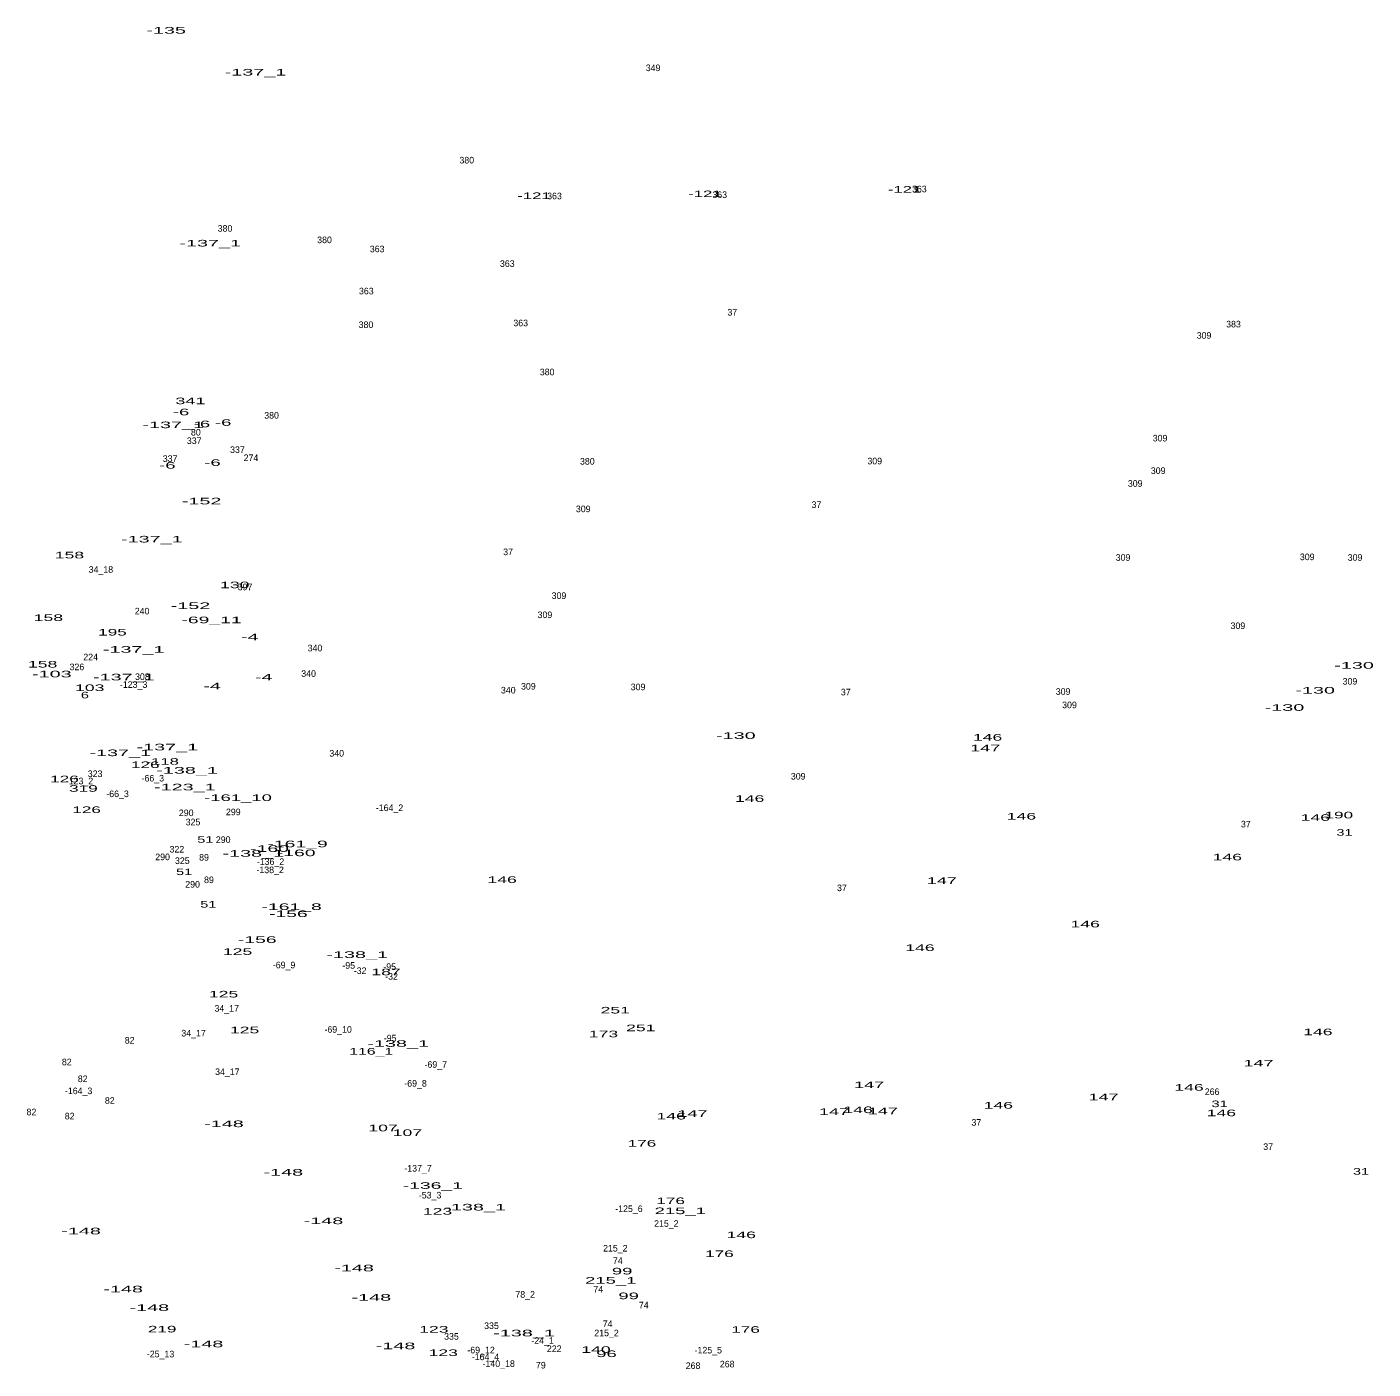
# Model space of a CAD drawing. Extents: x -662499 to -659675, y -1001682 to -998165.
# Drawn here: x -661283 to -660465, y -999146 to -998330 of the extents above; entities that cross this region are included whole.
import ezdxf
from ezdxf.enums import TextEntityAlignment as Align

# ---------------------------------------------------------------- set-up
doc = ezdxf.new("R2010")
doc.units = 0
doc.header["$LTSCALE"] = 1.6
doc.layers.add('24', color=7, linetype='Continuous')

msp = doc.modelspace()

# ---------------------------------------------------------------- texts
at = {"layer": '24'}
for s, width, p in [('-135', 2.25, (-661198.121, -998334.15)), ('-137_1', 2.25, (-661143.793, -998359.62)), ('-121', 1.9, (-660974.547, -998434.72)), ('-121', 1.9, (-660870.627, -998433.55)), ('-121', 1.9, (-660749.267, -998430.84)), ('-137_1', 2.25, (-661171.323, -998463.53)), ('-6', 2.1, (-661189.059, -998566.17)), ('341', 2.05, (-661183.393, -998559.39)), ('-137_1', 2.25, (-661193.813, -998573.96)), ('-6', 2.1, (-661176.359, -998573.44)), ('-6', 2.1, (-661163.469, -998572.57)), ('-6', 2.1, (-661197.399, -998598.56)), ('-6', 2.1, (-661169.959, -998596.91)), ('-152', 2.25, (-661176.561, -998620.3)), ('-137_1', 2.25, (-661206.803, -998643.45)), ('158', 2, (-661256.897, -998653.14)), ('130', 2, (-661156.424, -998671.24)), ('-152', 2.25, (-661183.341, -998683.91)), ('158', 2, (-661269.687, -998691.15)), ('-69_11', 2.2, (-661170.527, -998692.53)), ('195', 1.95, (-661230.753, -998700.01)), ('-4', 2.25, (-661147.28, -998702.86)), ('-137_1', 2.25, (-661217.853, -998710.46)), ('158', 2, (-661273.177, -998719.47)), ('-130', 2.25, (-660476.077, -998720.17)), ('-103', 2.25, (-661267.617, -998725.43)), ('-137_1', 2.25, (-661223.853, -998727.29)), ('-4', 2.25, (-661138.75, -998727.3)), ('103', 2, (-661244.584, -998733.76)), ('6', 1.65, (-661247.506, -998738.22)), ('-4', 2.25, (-661170.16, -998732.73)), ('-130', 2.25, (-660499.727, -998735.3)), ('-130', 2.25, (-660518.347, -998745.77)), ('-130', 2.25, (-660851.837, -998762.84)), ('-137_1', 2.25, (-661197.403, -998769.82)), ('147', 2.05, (-660700.258, -998770.41)), ('146', 2, (-660698.818, -998763.9)), ('-137_1', 2.25, (-661226.003, -998773.31)), ('-118', 1.9, (-661200.527, -998778.56)), ('126', 1.95, (-661210.843, -998780.58)), ('-138_1', 2.25, (-661185.407, -998783.93)), ('126', 1.95, (-661259.933, -998789.2)), ('319', 1.95, (-661248.403, -998794.98)), ('-123_1', 2.25, (-661186.747, -998794.14)), ('-161_10', 2.1, (-661154.445, -998800.59)), ('146', 2, (-660843.448, -998801.13)), ('126', 1.95, (-661246.473, -998807.89)), ('146', 2, (-660678.268, -998811.87)), ('190', 1.95, (-660485.349, -998811.16)), ('146', 2, (-660499.598, -998812.63)), ('51', 1.65, (-661174.317, -998825.98)), ('-161_9', 2.2, (-661118.237, -998828.7)), ('31', 1.65, (-660481.887, -998821.69)), ('-138_1', 2.25, (-661145.137, -998834.46)), ('-160', 2.2, (-661135.251, -998831.51)), ('-160', 2.2, (-661119.061, -998834.12)), ('146', 2, (-660553.108, -998836.68)), ('51', 1.65, (-661187.187, -998845.64)), ('146', 2, (-660993.888, -998850.39)), ('147', 2.05, (-660726.628, -998851)), ('51', 1.65, (-661172.477, -998865.39)), ('-161_8', 2.2, (-661121.833, -998866.84)), ('-156', 2.2, (-661123.845, -998871.13)), ('146', 2, (-660639.498, -998877.42)), ('125', 2, (-661154.697, -998894.14)), ('-156', 2.2, (-661142.745, -998886.84)), ('146', 2, (-660739.918, -998891.77)), ('-138_1', 2.25, (-661081.997, -998895.96)), ('187', 2, (-661064.473, -998906.48)), ('125', 2, (-661163.217, -998920)), ('251', 2, (-660925.127, -998929.74)), ('125', 2, (-661150.437, -998941.79)), ('251', 2, (-660909.617, -998940.51)), ('146', 2, (-660498.048, -998942.95)), ('-138_1', 2.25, (-661057.077, -998950.01)), ('173', 2, (-660932.283, -998944.19)), ('116_1', 1.8, (-661073.476, -998954.72)), ('147', 2.05, (-660534.118, -998961.94)), ('147', 2.05, (-660770.828, -998975.12)), ('147', 2.05, (-660628.338, -998982.49)), ('146', 2, (-660576.378, -998976.7)), ('147', 2.05, (-660792.158, -998991.41)), ('146', 2, (-660777.528, -998990.3)), ('147', 2.05, (-660762.488, -998991.03)), ('146', 2, (-660692.308, -998987.56)), ('146', 2, (-660556.718, -998992.19)), ('31', 1.65, (-660557.787, -998986.67)), ('-148', 2.25, (-661162.976, -998998.81)), ('146', 2, (-660891.138, -998994.17)), ('147', 2.05, (-660878.228, -998992.58)), ('107', 2, (-661066.279, -999001.33)), ('107', 2, (-661051.469, -999004.23)), ('176', 1.95, (-660908.917, -999010.69)), ('-148', 2.25, (-661126.916, -999028.29)), ('31', 1.65, (-660471.817, -999027.73)), ('-136_1', 2.2, (-661036.043, -999036.32)), ('-138_1', 2.25, (-661010.297, -999049.47)), ('176', 1.95, (-660891.467, -999045.6)), ('-148', 2.25, (-661102.486, -999057.77)), ('123', 2, (-661033.177, -999052.01)), ('215_1', 2.1, (-660885.615, -999051.7)), ('-148', 2.25, (-661249.826, -999063.98)), ('146', 2, (-660848.568, -999066.3)), ('176', 1.95, (-660861.807, -999077.79)), ('-148', 2.25, (-661083.876, -999086.47)), ('99', 2.1, (-660920.961, -999088.36)), ('215_1', 2.1, (-660927.875, -999093.97)), ('-148', 2.25, (-661224.236, -999099.27)), ('-148', 2.25, (-661073.406, -999104.32)), ('99', 2.1, (-660916.991, -999103.38)), ('-148', 2.25, (-661208.346, -999110.52)), ('219', 1.95, (-661200.573, -999123.61)), ('123', 2, (-661035.407, -999123.71)), ('-138_1', 2.25, (-660980.577, -999126)), ('176', 1.95, (-660845.947, -999123.83)), ('-148', 2.25, (-661175.386, -999132.63)), ('-148', 2.25, (-661058.676, -999133.79)), ('123', 2, (-661029.687, -999137.95)), ('140', 2, (-660936.859, -999136.03)), ('96', 2.1, (-660930.461, -999138.6))]:
    msp.add_text(s, height=4, dxfattribs=dict(at, width=width)).set_placement(p, align=Align.CENTER)
for s, p in [('349', (-660902.107, -998356.95)), ('380', (-661015.391, -998413.08)), ('363', (-660962.073, -998434.85)), ('363', (-660861.653, -998434.07)), ('363', (-660740.293, -998430.58)), ('380', (-661162.341, -998454.54)), ('380', (-661101.851, -998461.52)), ('363', (-661069.863, -998467.04)), ('363', (-660990.773, -998475.96)), ('363', (-661076.463, -998492.64)), ('37', (-660853.973, -998505.5)), ('380', (-661076.651, -998513.12)), ('363', (-660982.623, -998512.03)), ('383', (-660549.357, -998512.74)), ('309', (-660567.227, -998519.6)), ('380', (-660966.531, -998541.82)), ('380', (-661134.041, -998568.19)), ('80', (-661180.071, -998578.45)), ('309', (-660593.977, -998582.05)), ('337', (-661181.063, -998583.62)), ('337', (-661154.793, -998589.05)), ('337', (-661195.693, -998594.48)), ('274', (-661146.557, -998593.97)), ('380', (-660942.111, -998596.12)), ('309', (-660767.417, -998595.95)), ('309', (-660595.137, -998601.83)), ('309', (-660609.097, -998609.59)), ('37', (-660802.853, -998622.5)), ('309', (-660944.607, -998625.04)), ('37', (-660990.293, -998651.16)), ('309', (-660616.467, -998654.59)), ('309', (-660504.527, -998654.2)), ('309', (-660475.447, -998654.59)), ('34_18', (-661237.773, -998661.88)), ('397', (-661150.178, -998672.48)), ('309', (-660959.347, -998677.79)), ('240', (-661212.745, -998687.19)), ('309', (-660967.877, -998689.43)), ('309', (-660546.677, -998696.09)), ('340', (-661107.645, -998709.62)), ('326', (-661252.363, -998721.08)), ('224', (-661244.011, -998715.07)), ('308', (-661212.561, -998727.02)), ('340', (-661111.525, -998725.13)), ('309', (-660478.547, -998729.83)), ('-123_3', (-661217.896, -998731.82)), ('340', (-660990.165, -998735.22)), ('309', (-660977.957, -998732.87)), ('309', (-660911.267, -998733.26)), ('37', (-660785.033, -998736.39)), ('309', (-660652.917, -998736.04)), ('309', (-660649.037, -998744.19)), ('340', (-661094.465, -998773.62)), ('323', (-661241.307, -998786.05)), ('309', (-660813.937, -998787.56)), ('-123_2', (-661250.806, -998790.44)), ('-66_3', (-661206.233, -998788.73)), ('-66_3', (-661227.653, -998798.23)), ('290', (-661185.927, -998809.79)), ('299', (-661157.308, -998809.23)), ('-164_2', (-661062.366, -998806.72)), ('325', (-661181.797, -998815.39)), ('37', (-660541.843, -998816.65)), ('290', (-661163.437, -998826.09)), ('290', (-661200.277, -998836.56)), ('322', (-661191.587, -998831.9)), ('89', (-661175.093, -998836.84)), ('325', (-661188.287, -998838.86)), ('-138_2', (-661134.906, -998844.45)), ('-136_2', (-661134.682, -998839.47)), ('290', (-661182.047, -998853.24)), ('89', (-661172.093, -998850.5)), ('37', (-660787.363, -998855.39)), ('-69_9', (-661126.438, -998902.29)), ('-95', (-661087.16, -998902.53)), ('-32', (-661080.205, -998905.75)), ('-95', (-661062.25, -998903.31)), ('-32', (-661061.105, -998909.24)), ('34_17', (-661161.308, -998928.63)), ('-69_10', (-661093.571, -998941.45)), ('82', (-661220.277, -998948.03)), ('34_17', (-661181.448, -998943.72)), ('-95', (-661061.96, -998946.72)), ('82', (-661258.517, -998961.2)), ('34_17', (-661160.918, -998967.17)), ('-69_7', (-661034.238, -998962.76)), ('82', (-661248.837, -998971.47)), ('-69_8', (-661046.543, -998974.21)), ('-164_3', (-661251.326, -998978.77)), ('266', (-660562.338, -998979.3)), ('82', (-661280.007, -998991.61)), ('82', (-661232.377, -998984.64)), ('82', (-661256.777, -998994.13)), ('37', (-660705.653, -998997.96)), ('37', (-660528.283, -999012.68)), ('-137_7', (-661045.017, -999025.84)), ('-53_3', (-661037.682, -999042.18)), ('-125_6', (-660916.822, -999050.44)), ('215_2', (-660894.089, -999059.4)), ('215_2', (-660925.109, -999074.43)), ('74', (-660923.587, -999081.98)), ('78_2', (-660979.9, -999102.49)), ('74', (-660935.497, -999099.42)), ('74', (-660907.807, -999109.01)), ('335', (-661000.377, -999121.55)), ('74', (-660929.777, -999120.34)), ('335', (-661024.707, -999128.04)), ('-24_1', (-660969.29, -999130.52)), ('215_2', (-660930.439, -999125.93)), ('-25_13', (-661201.516, -999138.73)), ('-69_12', (-661006.697, -999136.33)), ('222', (-660962.227, -999135.51)), ('-125_5', (-660868.596, -999136.39)), ('-164_4', (-661004.02, -999140.46)), ('-140_18', (-660995.997, -999144.58)), ('79', (-660970.388, -999145.53)), ('268', (-660877.843, -999145.83)), ('268', (-660857.103, -999144.86))]:
    msp.add_text(s, height=4, dxfattribs=at).set_placement(p, align=Align.CENTER)

doc.saveas('drawing.dxf')
